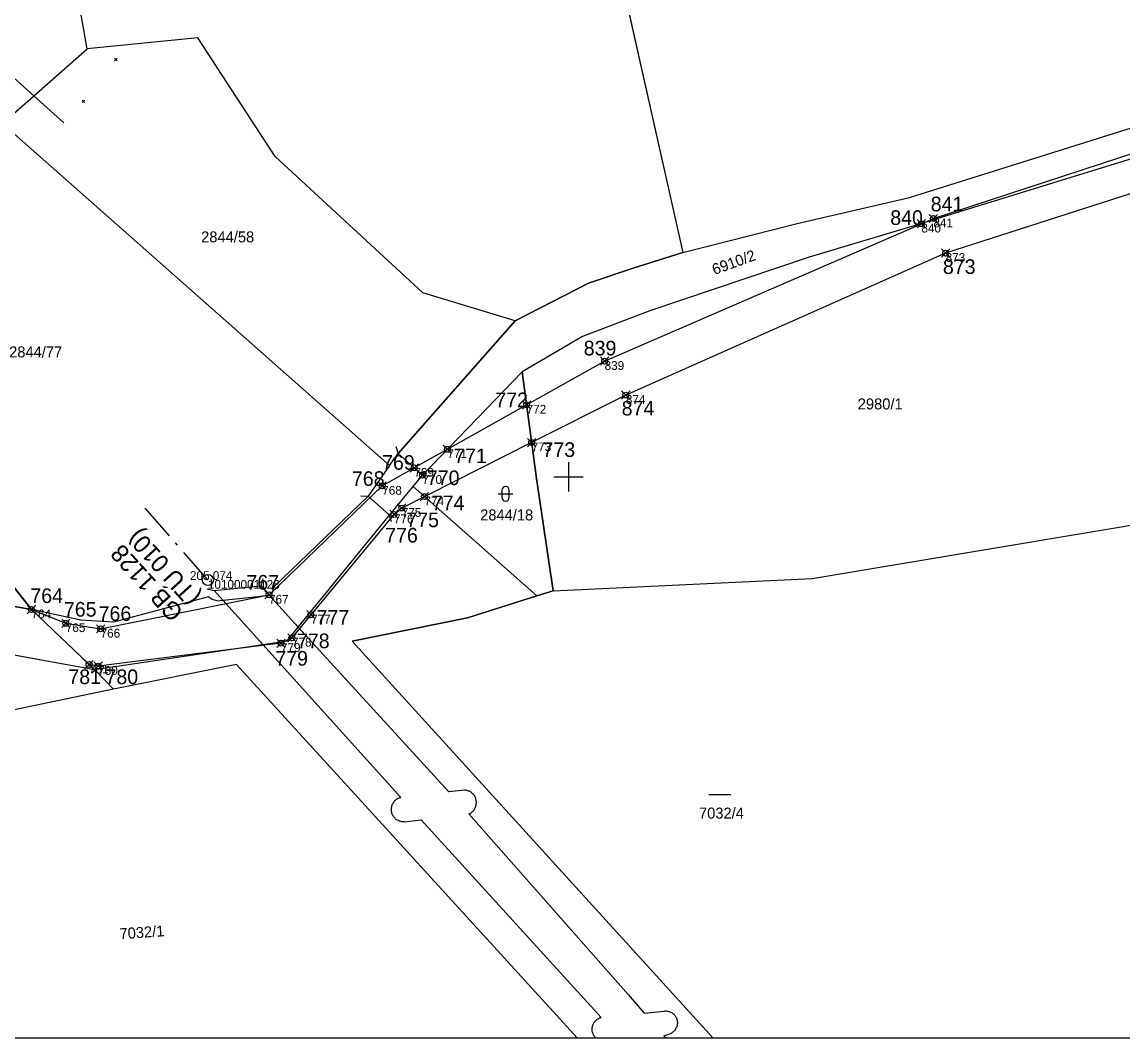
# Model space of a CAD drawing. Extents: x -800194 to -799078, y -1007177 to -1006597.
# Drawn here: x -799674.6 to -799524.3, y -1007176.6 to -1007037.9 of the extents above; entities that cross this region are included whole.
import ezdxf

# ---------------------------------------------------------------- set-up
doc = ezdxf.new("R2010")
doc.units = 0
for name, color, linetype in [('Dočasné zábory', 7, 'Continuous'), ('Legenda 1', 7, 'Continuous'), ('Obvod stavby', 7, 'Continuous'), ('Ramove udaje', 7, 'Continuous'), ('Vrstva 49', 7, 'Continuous'), ('Vrstva 53', 7, 'Continuous'), ('Vrstva 55', 7, 'Continuous'), ('Vrstva 56', 7, 'Continuous'), ('Vrstva 57', 7, 'Continuous'), ('Vrstva 58', 7, 'Continuous'), ('Vrstva 60', 7, 'Continuous'), ('Vrstva 61', 7, 'Continuous'), ('Vrstva 63', 7, 'Continuous')]:
    doc.layers.add(name, color=color, linetype=linetype)

msp = doc.modelspace()

# ---------------------------------------------------------------- linework, layer by layer
at = {"layer": 'Dočasné zábory'}
for p, q in [((-799550.72, -1007065.3), (-799549.59, -1007064.17)), ((-799550.72, -1007064.17), (-799549.59, -1007065.3)), ((-799552.37, -1007066.02), (-799551.23, -1007064.89)), ((-799552.37, -1007064.89), (-799551.23, -1007066.02)), ((-799549.05, -1007070.03), (-799547.92, -1007068.89)), ((-799549.05, -1007068.89), (-799547.92, -1007070.03)), ((-799595.63, -1007084.79), (-799594.49, -1007083.65)), ((-799595.63, -1007083.65), (-799594.49, -1007084.79)), ((-799592.73, -1007089.41), (-799591.59, -1007088.28)), ((-799592.73, -1007088.28), (-799591.59, -1007089.41)), ((-799616.53, -1007096.26), (-799621.05, -1007098.8))]:
    msp.add_line(p, q, dxfattribs=at)
for points in [[(-799551.8, -1007065.45), (-799550.16, -1007064.74), (-799440.86, -1007028.93), (-799429.23, -1007018.29), (-799423.8, -1007012.71), (-799421.5, -1007009.7), (-799412.39, -1007002.78), (-799410.56, -1007001.81), (-799396.88, -1006994.58), (-799395.92, -1006994.07), (-799394.94, -1006993.03), (-799394.95, -1006991.66), (-799395.98, -1006986.65), (-799406.07, -1006937.82), (-799408.05, -1006924.38), (-799411.99, -1006900.28), (-799413.45, -1006897.92)], [(-799408.65, -1007008.83), (-799412.5, -1007010.44), (-799420, -1007017.54), (-799436.16, -1007033.34), (-799548.49, -1007069.46), (-799592.16, -1007088.85), (-799605.02, -1007095.33)], [(-799605.71, -1007090.19), (-799595.06, -1007084.22), (-799551.8, -1007065.45)]]:
    msp.add_lwpolyline(points, dxfattribs=at)
for centre in [(-799551.8, -1007065.45), (-799550.16, -1007064.74), (-799548.49, -1007069.46), (-799595.06, -1007084.22), (-799592.16, -1007088.85)]:
    msp.add_circle(centre, 0.4, dxfattribs=at)
at = {"layer": 'Legenda 1'}
msp.add_lwpolyline([(-800193.4, -1007176.65), (-799312.4, -1007176.65), (-799312.4, -1006766.65), (-800193.4, -1006766.65)], close=True, dxfattribs=at)
at = {"layer": 'Obvod stavby'}
for p, q in [((-799606.27, -1007090.76), (-799605.14, -1007089.63)), ((-799606.27, -1007089.63), (-799605.14, -1007090.76)), ((-799617.1, -1007096.83), (-799615.96, -1007095.7)), ((-799617.1, -1007095.7), (-799615.96, -1007096.83)), ((-799605.58, -1007095.9), (-799604.45, -1007094.76)), ((-799605.58, -1007094.76), (-799604.45, -1007095.9)), ((-799621.62, -1007099.37), (-799620.48, -1007098.23)), ((-799621.62, -1007098.23), (-799620.48, -1007099.37)), ((-799620.51, -1007100.36), (-799619.37, -1007099.22)), ((-799620.51, -1007099.22), (-799619.37, -1007100.36)), ((-799626, -1007101.82), (-799624.87, -1007100.69)), ((-799626, -1007100.69), (-799624.87, -1007101.82)), ((-799620.23, -1007103.28), (-799619.1, -1007102.15)), ((-799620.23, -1007102.15), (-799619.1, -1007103.28)), ((-799624.39, -1007105.72), (-799623.26, -1007104.59)), ((-799624.39, -1007104.59), (-799623.26, -1007105.72)), ((-799623.33, -1007104.84), (-799622.2, -1007103.71)), ((-799623.33, -1007103.71), (-799622.2, -1007104.84)), ((-799641.46, -1007116.7), (-799640.33, -1007115.57)), ((-799641.46, -1007115.57), (-799640.33, -1007116.7)), ((-799673.9, -1007118.71), (-799672.76, -1007117.57)), ((-799673.9, -1007117.57), (-799672.76, -1007118.71)), ((-799635.72, -1007119.42), (-799634.59, -1007118.29)), ((-799635.72, -1007118.29), (-799634.59, -1007119.42)), ((-799669.2, -1007120.59), (-799668.07, -1007119.46)), ((-799669.2, -1007119.46), (-799668.07, -1007120.59)), ((-799664.45, -1007121.34), (-799663.32, -1007120.21)), ((-799664.45, -1007120.21), (-799663.32, -1007121.34)), ((-799639.82, -1007123.31), (-799638.69, -1007122.17)), ((-799639.82, -1007122.17), (-799638.69, -1007123.31)), ((-799638.32, -1007122.57), (-799637.19, -1007121.44)), ((-799638.32, -1007121.44), (-799637.19, -1007122.57)), ((-799666.04, -1007126.22), (-799664.91, -1007125.08)), ((-799666.04, -1007125.08), (-799664.91, -1007126.22)), ((-799664.79, -1007126.42), (-799663.65, -1007125.29)), ((-799664.79, -1007125.29), (-799663.65, -1007126.42))]:
    msp.add_line(p, q, dxfattribs=at)
msp.add_lwpolyline([(-799715.54, -1007076.14), (-799696.4, -1007096.25), (-799680.35, -1007116.92), (-799673.33, -1007118.14), (-799693.11, -1007093.25), (-799714.14, -1007072.19)], dxfattribs=at)
msp.add_lwpolyline([(-799673.33, -1007118.14), (-799668.64, -1007120.02), (-799663.88, -1007120.77), (-799640.89, -1007116.14), (-799625.43, -1007101.26), (-799621.05, -1007098.8), (-799619.94, -1007099.79), (-799616.53, -1007096.26), (-799605.71, -1007090.19), (-799605.02, -1007095.33), (-799622.76, -1007104.28), (-799623.83, -1007105.16), (-799635.16, -1007118.86), (-799637.76, -1007122), (-799639.26, -1007122.74), (-799664.22, -1007125.86), (-799665.47, -1007125.65)], close=True, dxfattribs=at)
for centre in [(-799605.71, -1007090.19), (-799605.02, -1007095.33), (-799616.53, -1007096.26), (-799621.05, -1007098.8), (-799619.94, -1007099.79), (-799625.43, -1007101.26), (-799619.66, -1007102.72), (-799623.83, -1007105.16), (-799622.76, -1007104.28), (-799640.89, -1007116.14), (-799673.33, -1007118.14), (-799668.64, -1007120.02), (-799635.16, -1007118.86), (-799663.88, -1007120.77), (-799639.26, -1007122.74), (-799637.76, -1007122), (-799665.47, -1007125.65), (-799664.22, -1007125.86)]:
    msp.add_circle(centre, 0.4, dxfattribs=at)
at = {"layer": 'Ramove udaje'}
for p, q in [((-799600, -1007098), (-799600, -1007102)), ((-799602, -1007100), (-799600, -1007100)), ((-799600, -1007100), (-799598, -1007100))]:
    msp.add_line(p, q, dxfattribs=at)
at = {"layer": 'Vrstva 49'}
for p, q in [((-799661.98, -1007042.84), (-799661.62, -1007043.19)), ((-799661.98, -1007043.19), (-799661.62, -1007042.84)), ((-799666.42, -1007048.56), (-799666.07, -1007048.91)), ((-799666.42, -1007048.91), (-799666.07, -1007048.56))]:
    msp.add_line(p, q, dxfattribs=at)
msp.add_lwpolyline([(-799716.25, -1006997.26), (-799711.44, -1007004.24), (-799711.11, -1007006.25), (-799707.44, -1007011.02), (-799702.58, -1007019.59), (-799698.24, -1007027), (-799684.87, -1007037.35), (-799668.9, -1007051.67)], dxfattribs=at)
at = {"layer": 'Vrstva 53'}
for points in [[(-799521.98, -1006977.8), (-799546.71, -1006987.83), (-799572.22, -1006995.8), (-799583.97, -1006998.26), (-799599.63, -1007001.65), (-799584.37, -1007069.36), (-799591.04, -1007071.48), (-799597.25, -1007073.58), (-799607.27, -1007078.7), (-799623.27, -1007096.82), (-799619.94, -1007099.79), (-799606.31, -1007085.7), (-799604.36, -1007100.23), (-799602.09, -1007115.59), (-799604.31, -1007116.28), (-799613.8, -1007119.26), (-799629.52, -1007122.44), (-799580.26, -1007176.65)], [(-799713.93, -1007117.37), (-799664.74, -1007126.35), (-799673.33, -1007118.14), (-799714.71, -1007110.97)], [(-799598.82, -1007176.65), (-799645.33, -1007125.63), (-799662.13, -1007129.03), (-799692.74, -1007135.4)]]:
    msp.add_lwpolyline(points, dxfattribs=at)
at = {"layer": 'Vrstva 55'}
for p, q in [((-799599.63, -1007001.65), (-799584.37, -1007069.36)), ((-799677.3, -1007051.77), (-799665.73, -1007041.59)), ((-799712.65, -1007067.97), (-799673.33, -1007118.14)), ((-799623.27, -1007096.82), (-799607.27, -1007078.7)), ((-799606.31, -1007085.7), (-799619.94, -1007099.79)), ((-799619.94, -1007099.79), (-799623.27, -1007096.82)), ((-799673.33, -1007118.14), (-799714.71, -1007110.97)), ((-799613.8, -1007119.26), (-799604.31, -1007116.28)), ((-799604.31, -1007116.28), (-799602.09, -1007115.59)), ((-799713.93, -1007117.37), (-799664.74, -1007126.35)), ((-799673.33, -1007118.14), (-799664.74, -1007126.35)), ((-799664.74, -1007126.35), (-799662.13, -1007129.03))]:
    msp.add_line(p, q, dxfattribs=at)
for points in [[(-799409.68, -1007006.29), (-799420, -1007017.54), (-799425.58, -1007022.42), (-799434.1, -1007028.26), (-799444.02, -1007032.78), (-799478.24, -1007042.75), (-799552.64, -1007065.71), (-799567.11, -1007070.01), (-799588.9, -1007077.33), (-799598.09, -1007080.87), (-799606.31, -1007085.7)], [(-799665.73, -1007041.59), (-799667.81, -1007029.7), (-799667.22, -1007009.16)], [(-799584.37, -1007069.36), (-799568.78, -1007065.44), (-799553.44, -1007061.89), (-799480.9, -1007039.1), (-799478.14, -1007038.23)], [(-799607.27, -1007078.7), (-799619.88, -1007074.91), (-799640.06, -1007056.27), (-799650.63, -1007040.08), (-799665.73, -1007041.59)], [(-799677.3, -1007051.77), (-799624.44, -1007098.49), (-799623.27, -1007096.82)], [(-799607.27, -1007078.7), (-799597.25, -1007073.58), (-799591.04, -1007071.48), (-799584.37, -1007069.36)], [(-799602.09, -1007115.59), (-799604.36, -1007100.23), (-799606.31, -1007085.7)], [(-799602.09, -1007115.59), (-799566.73, -1007113.9), (-799505.74, -1007103.69), (-799454.59, -1007096.36)], [(-799604.31, -1007116.28), (-799621.22, -1007101.34), (-799619.94, -1007099.79)], [(-799580.26, -1007176.65), (-799629.52, -1007122.44), (-799613.8, -1007119.26)], [(-799598.82, -1007176.65), (-799645.33, -1007125.63), (-799662.13, -1007129.03)], [(-799662.13, -1007129.03), (-799692.74, -1007135.4), (-799710.71, -1007144.99), (-799727.84, -1007152.76)]]:
    msp.add_lwpolyline(points, dxfattribs=at)
at = {"layer": 'Vrstva 56'}
for p, q in [((-799623.58, -1007095.87), (-799623.27, -1007096.82)), ((-799624.44, -1007098.49), (-799626.23, -1007101.04)), ((-799618.96, -1007099.98), (-799619.94, -1007099.79)), ((-799626.23, -1007101.04), (-799627.37, -1007102.67)), ((-799624.45, -1007105.23), (-799621.22, -1007101.34)), ((-799640.29, -1007115.09), (-799627.37, -1007102.67)), ((-799628.37, -1007102.62), (-799627.37, -1007102.67)), ((-799627.37, -1007102.67), (-799624.45, -1007105.23)), ((-799636.89, -1007120.54), (-799624.45, -1007105.23)), ((-799624.14, -1007106.18), (-799624.45, -1007105.23)), ((-799649.34, -1007115.32), (-799648.37, -1007115.55)), ((-799648.37, -1007115.55), (-799645.26, -1007115.24)), ((-799645.26, -1007115.24), (-799641.97, -1007114.92)), ((-799641.73, -1007113.95), (-799641.97, -1007114.92)), ((-799641.97, -1007114.92), (-799640.86, -1007116.19)), ((-799640.3, -1007115.68), (-799640.29, -1007115.09)), ((-799649.14, -1007116.42), (-799662.13, -1007119.88)), ((-799648.66, -1007116.78), (-799649.14, -1007116.42)), ((-799647.98, -1007116.94), (-799648.66, -1007116.78)), ((-799648.37, -1007115.55), (-799647.19, -1007116.86)), ((-799647.98, -1007116.94), (-799647.19, -1007116.86)), ((-799647.19, -1007116.86), (-799644.09, -1007116.53)), ((-799647.19, -1007116.86), (-799641.73, -1007122.91)), ((-799644.09, -1007116.53), (-799640.86, -1007116.19)), ((-799640.86, -1007116.19), (-799640.3, -1007115.68)), ((-799636.89, -1007120.54), (-799640.86, -1007116.19)), ((-799666.59, -1007119.58), (-799673.33, -1007118.14)), ((-799662.13, -1007119.88), (-799666.59, -1007119.58)), ((-799638.42, -1007122.42), (-799636.89, -1007120.54)), ((-799616.33, -1007143.04), (-799636.89, -1007120.54)), ((-799641.73, -1007122.91), (-799638.71, -1007122.46)), ((-799638.71, -1007122.46), (-799638.42, -1007122.42)), ((-799664.74, -1007126.35), (-799641.73, -1007122.91)), ((-799641.73, -1007122.91), (-799622.9, -1007143.79)), ((-799614.21, -1007142.8), (-799616.33, -1007143.04)), ((-799622.43, -1007147.14), (-799620.11, -1007146.85)), ((-799620.11, -1007146.85), (-799595.55, -1007173.85)), ((-799613.58, -1007146.05), (-799591.84, -1007170.73)), ((-799591.84, -1007170.73), (-799589.67, -1007173.25)), ((-799589.67, -1007173.25), (-799586.91, -1007172.97)), ((-799586.99, -1007176.37), (-799586.23, -1007176.11)), ((-799586.99, -1007176.37), (-799586.72, -1007176.65))]:
    msp.add_line(p, q, dxfattribs=at)
for points in [[(-799622.43, -1007147.14), (-799622.55, -1007147.14), (-799622.66, -1007147.13), (-799622.78, -1007147.11), (-799622.89, -1007147.09), (-799623, -1007147.06), (-799623.11, -1007147.02), (-799623.21, -1007146.97), (-799623.32, -1007146.92), (-799623.42, -1007146.86), (-799623.51, -1007146.79), (-799623.6, -1007146.72), (-799623.68, -1007146.64), (-799623.76, -1007146.56), (-799623.83, -1007146.47), (-799623.9, -1007146.37), (-799623.96, -1007146.27), (-799624.01, -1007146.17), (-799624.06, -1007146.07), (-799624.1, -1007145.96), (-799624.13, -1007145.84), (-799624.15, -1007145.73), (-799624.17, -1007145.62), (-799624.18, -1007145.5), (-799624.18, -1007145.39), (-799624.17, -1007145.27), (-799624.16, -1007145.16), (-799624.13, -1007145.04), (-799624.1, -1007144.93), (-799624.07, -1007144.82), (-799624.02, -1007144.72), (-799623.97, -1007144.61), (-799623.91, -1007144.52), (-799623.84, -1007144.42), (-799623.77, -1007144.33), (-799623.69, -1007144.24), (-799623.61, -1007144.17), (-799623.52, -1007144.09), (-799623.43, -1007144.03), (-799623.33, -1007143.96), (-799623.22, -1007143.91), (-799623.12, -1007143.86), (-799623.01, -1007143.82), (-799622.9, -1007143.79)], [(-799613.58, -1007146.05), (-799613.48, -1007146), (-799613.38, -1007145.94), (-799613.28, -1007145.88), (-799613.19, -1007145.81), (-799613.11, -1007145.74), (-799613.03, -1007145.66), (-799612.95, -1007145.57), (-799612.88, -1007145.48), (-799612.82, -1007145.38), (-799612.76, -1007145.28), (-799612.71, -1007145.18), (-799612.67, -1007145.07), (-799612.64, -1007144.97), (-799612.61, -1007144.85), (-799612.59, -1007144.74), (-799612.58, -1007144.63), (-799612.57, -1007144.52), (-799612.57, -1007144.4), (-799612.58, -1007144.29), (-799612.6, -1007144.17), (-799612.63, -1007144.06), (-799612.66, -1007143.95), (-799612.7, -1007143.85), (-799612.75, -1007143.74), (-799612.8, -1007143.64), (-799612.86, -1007143.55), (-799612.93, -1007143.45), (-799613, -1007143.36), (-799613.08, -1007143.28), (-799613.17, -1007143.21), (-799613.25, -1007143.14), (-799613.35, -1007143.07), (-799613.45, -1007143.01), (-799613.55, -1007142.96), (-799613.65, -1007142.91), (-799613.76, -1007142.88), (-799613.87, -1007142.85), (-799613.98, -1007142.82), (-799614.1, -1007142.81), (-799614.21, -1007142.8)], [(-799596.25, -1007176.65), (-799596.26, -1007176.64), (-799596.34, -1007176.56), (-799596.41, -1007176.47), (-799596.48, -1007176.38), (-799596.54, -1007176.29), (-799596.59, -1007176.19), (-799596.64, -1007176.09), (-799596.68, -1007175.98), (-799596.71, -1007175.87), (-799596.74, -1007175.76), (-799596.76, -1007175.65), (-799596.77, -1007175.54), (-799596.77, -1007175.43), (-799596.76, -1007175.32), (-799596.75, -1007175.2), (-799596.73, -1007175.09), (-799596.7, -1007174.98), (-799596.67, -1007174.88), (-799596.63, -1007174.77), (-799596.58, -1007174.67), (-799596.52, -1007174.57), (-799596.46, -1007174.48), (-799596.39, -1007174.39), (-799596.31, -1007174.31), (-799596.23, -1007174.23), (-799596.15, -1007174.15), (-799596.06, -1007174.09), (-799595.96, -1007174.03), (-799595.86, -1007173.97), (-799595.76, -1007173.92), (-799595.66, -1007173.88), (-799595.55, -1007173.85)], [(-799586.91, -1007172.97), (-799586.8, -1007172.96), (-799586.69, -1007172.96), (-799586.57, -1007172.97), (-799586.46, -1007172.98), (-799586.35, -1007173.01), (-799586.24, -1007173.04), (-799586.14, -1007173.08), (-799586.03, -1007173.12), (-799585.93, -1007173.17), (-799585.84, -1007173.23), (-799585.74, -1007173.3), (-799585.66, -1007173.37), (-799585.58, -1007173.45), (-799585.5, -1007173.53), (-799585.43, -1007173.62), (-799585.37, -1007173.71), (-799585.31, -1007173.81), (-799585.26, -1007173.91), (-799585.22, -1007174.02), (-799585.18, -1007174.12), (-799585.16, -1007174.23), (-799585.14, -1007174.34), (-799585.12, -1007174.46), (-799585.12, -1007174.57), (-799585.12, -1007174.68), (-799585.13, -1007174.79), (-799585.15, -1007174.91), (-799585.18, -1007175.02), (-799585.21, -1007175.12), (-799585.26, -1007175.23), (-799585.31, -1007175.33), (-799585.36, -1007175.43), (-799585.42, -1007175.52), (-799585.49, -1007175.61), (-799585.57, -1007175.69), (-799585.65, -1007175.77), (-799585.73, -1007175.84), (-799585.83, -1007175.91), (-799585.92, -1007175.97), (-799586.02, -1007176.03), (-799586.12, -1007176.07), (-799586.23, -1007176.11)]]:
    msp.add_lwpolyline(points, dxfattribs=at)
at = {"layer": 'Vrstva 58'}
for p, q in [((-799609.08, -1007101.83), (-799609.08, -1007102.84)), ((-799608.08, -1007102.84), (-799608.08, -1007101.83)), ((-799609.58, -1007102.33), (-799607.58, -1007102.33)), ((-799580.84, -1007143.4), (-799577.84, -1007143.4))]:
    msp.add_line(p, q, dxfattribs=at)
for centre, start, end in [((-799608.58, -1007101.83), 0, 180), ((-799608.58, -1007102.83), 180, 359.9879)]:
    msp.add_arc(centre, 0.5, start, end, dxfattribs=at)
at = {"layer": 'Vrstva 60'}
for p, q in [((-799551.8, -1007065.45), (-799551.8, -1007065.45)), ((-799550.16, -1007064.74), (-799550.16, -1007064.74)), ((-799548.49, -1007069.46), (-799548.49, -1007069.46)), ((-799595.06, -1007084.22), (-799595.06, -1007084.22)), ((-799592.16, -1007088.85), (-799592.16, -1007088.85)), ((-799605.71, -1007090.19), (-799605.71, -1007090.19)), ((-799605.02, -1007095.33), (-799605.02, -1007095.33)), ((-799616.53, -1007096.26), (-799616.53, -1007096.26)), ((-799621.05, -1007098.8), (-799621.05, -1007098.8)), ((-799619.94, -1007099.79), (-799619.94, -1007099.79)), ((-799625.43, -1007101.26), (-799625.43, -1007101.26)), ((-799619.66, -1007102.71), (-799619.66, -1007102.71)), ((-799622.76, -1007104.28), (-799622.76, -1007104.28)), ((-799623.83, -1007105.16), (-799623.83, -1007105.16)), ((-799649.24, -1007114.1), (-799649.24, -1007114.1)), ((-799640.89, -1007116.14), (-799640.89, -1007116.14)), ((-799673.33, -1007118.14), (-799673.33, -1007118.14)), ((-799635.16, -1007118.86), (-799635.16, -1007118.86)), ((-799668.64, -1007120.02), (-799668.64, -1007120.02)), ((-799663.89, -1007120.77), (-799663.89, -1007120.77)), ((-799639.26, -1007122.74), (-799639.26, -1007122.74)), ((-799637.76, -1007122), (-799637.76, -1007122)), ((-799665.47, -1007125.65), (-799665.47, -1007125.65)), ((-799664.22, -1007125.86), (-799664.22, -1007125.86))]:
    msp.add_line(p, q, dxfattribs=at)
at = {"layer": 'Vrstva 63'}
for p, q in [((-799654.5, -1007108.07), (-799657.79, -1007104.31)), ((-799653.38, -1007109.35), (-799653.65, -1007109.05)), ((-799649.24, -1007114.1), (-799652.53, -1007110.33)), ((-799649.21, -1007114.13), (-799649.27, -1007114.06))]:
    msp.add_line(p, q, dxfattribs=at)
msp.add_circle((-799649.24, -1007114.1), 0.756, dxfattribs=at)

# ---------------------------------------------------------------- texts
at = {"layer": 'Dočasné zábory'}
for s, p in [('841', (-799550.52, -1007063.76)), ('840', (-799556.05, -1007065.62)), ('873', (-799548.86, -1007072.31)), ('839', (-799597.91, -1007083.44)), ('874', (-799592.73, -1007091.64))]:
    msp.add_text(s, height=2, rotation=360, dxfattribs=at).set_placement(p)
at = {"layer": 'Obvod stavby'}
for s, p in [('772', (-799609.99, -1007090.51)), ('773', (-799603.54, -1007097.3)), ('769', (-799625.45, -1007099.05)), ('771', (-799615.61, -1007098.15)), ('768', (-799629.57, -1007101.26)), ('770', (-799619.33, -1007101.15)), ('774', (-799618.66, -1007104.57)), ('775', (-799622.14, -1007106.89)), ('776', (-799625.03, -1007108.99)), ('767', (-799643.97, -1007115.42)), ('764', (-799673.48, -1007117.25)), ('765', (-799668.9, -1007119.11)), ('766', (-799664.16, -1007119.69)), ('777', (-799634.4, -1007120.21)), ('778', (-799637.07, -1007123.42)), ('779', (-799640.03, -1007125.8)), ('781', (-799668.29, -1007128.32)), ('780', (-799663.22, -1007128.32))]:
    msp.add_text(s, height=2, rotation=360, dxfattribs=at).set_placement(p)
at = {"layer": 'Vrstva 57'}
for s, p in [('2844/58', (-799650.16, -1007068)), ('2844/77', (-799676.38, -1007083.71)), ('2980/1', (-799560.49, -1007090.81)), ('2844/18', (-799612.06, -1007105.97)), ('7032/4', (-799582.17, -1007146.69))]:
    msp.add_text(s, height=1.5, dxfattribs=at).set_placement(p)
for s, rotation, p in [('6910/2', 20, (-799580.05, -1007072.47)), ('7032/1', 4, (-799661.25, -1007163.18))]:
    msp.add_text(s, height=1.5, rotation=rotation, dxfattribs=at).set_placement(p)
at = {"layer": 'Vrstva 60'}
for s, p in [('840', (-799551.8, -1007066.65)), ('841', (-799550.16, -1007065.94)), ('873', (-799548.49, -1007070.66)), ('839', (-799595.06, -1007085.42)), ('874', (-799592.16, -1007090.05)), ('772', (-799605.71, -1007091.39)), ('773', (-799605.02, -1007096.53)), ('771', (-799616.53, -1007097.46)), ('769', (-799621.05, -1007100)), ('770', (-799619.94, -1007100.99)), ('768', (-799625.43, -1007102.46)), ('774', (-799619.66, -1007103.92)), ('775', (-799622.76, -1007105.48)), ('776', (-799623.83, -1007106.36)), ('10100001128', (-799649.24, -1007115.3)), ('767', (-799640.89, -1007117.34)), ('764', (-799673.33, -1007119.34)), ('777', (-799635.16, -1007120.06)), ('765', (-799668.64, -1007121.22)), ('766', (-799663.89, -1007121.97)), ('779', (-799639.26, -1007123.94)), ('778', (-799637.76, -1007123.2)), ('781', (-799665.47, -1007126.85)), ('780', (-799664.22, -1007127.06))]:
    msp.add_text(s, height=1.2, dxfattribs=at).set_placement(p)
at = {"layer": 'Vrstva 61'}
msp.add_text('205.074', height=1.2, dxfattribs=at).set_placement((-799651.69, -1007114.1))
at = {"layer": 'Vrstva 63'}
for s, p in [('(TÚ 010)', (-799650.14, -1007116.32)), ('GB 1128', (-799652.44, -1007118.41))]:
    msp.add_text(s, height=2.4, rotation=132.2013, dxfattribs=at).set_placement(p)

doc.saveas('drawing.dxf')
